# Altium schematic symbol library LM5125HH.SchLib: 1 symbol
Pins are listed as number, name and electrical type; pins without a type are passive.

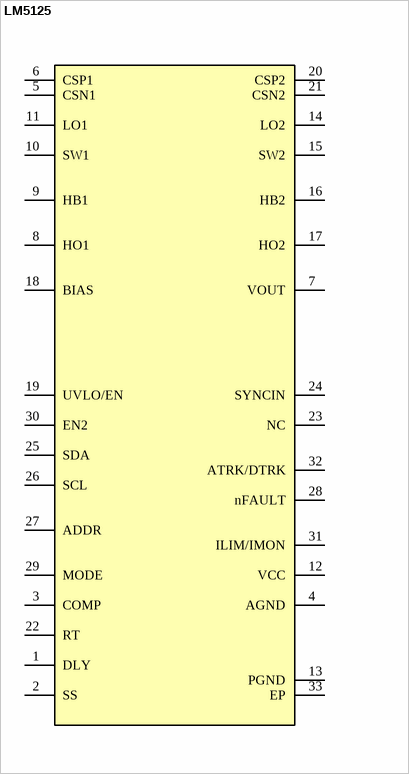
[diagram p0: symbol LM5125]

## LM5125
designator U?, comment LM5125-Q1RHB
Manufacturer: Used in BOM report; CompType: Used in some BOM reports.  Useful for finding later.
footprint PCBComponent_1
pins: 1 DLY, 2 SS, 3 COMP, 4 AGND, 5 CSN1, 6 CSP1, 7 VOUT, 8 HO1, 9 HB1, 10 SW1, 11 LO1, 12 VCC, 13 PGND, 14 LO2, 15 SW2, 16 HB2, 17 HO2, 18 BIAS, 19 UVLO/EN, 20 CSP2, 21 CSN2, 22 RT, 23 NC, 24 SYNCIN, 25 SDA, 26 SCL, 27 ADDR, 28 nFAULT, 29 MODE, 30 EN2, 31 ILIM/IMON, 32 ATRK/DTRK, 33 EP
